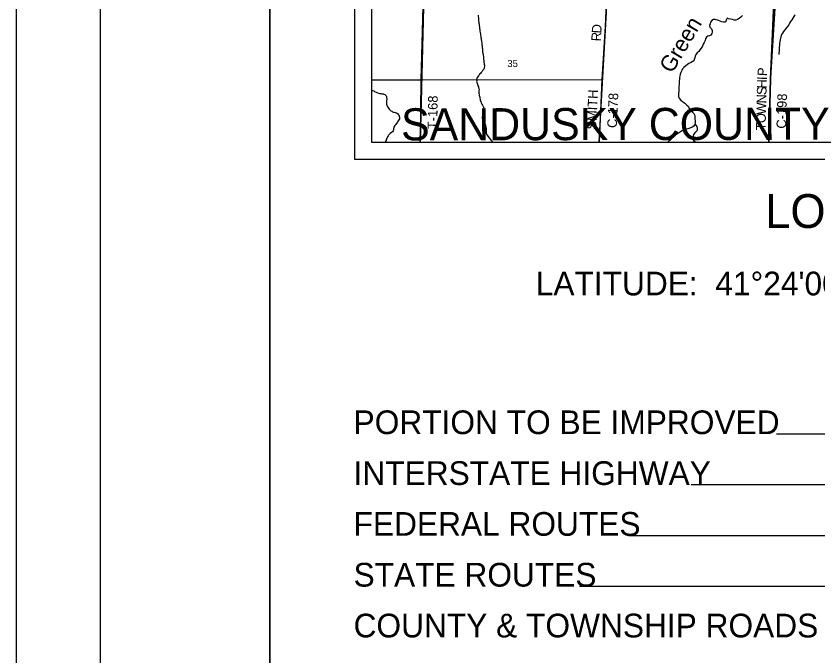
# Model space of a CAD drawing. Extents: x 36.7 to 70.7, y 0 to 22.
# Drawn here: x 36.693 to 41.432, y 11.064 to 14.842 of the extents above; entities that cross this region are included whole.
import ezdxf

# ---------------------------------------------------------------- set-up
doc = ezdxf.new("R2010")
doc.units = 0
for name, color, linetype in [('Default', 7, 'Continuous'), ('GM_X_County_Road', 7, 'Continuous'), ('GM_X_County_Road_Text', 7, 'Continuous'), ('GM_X_County_Text', 7, 'Continuous'), ('GM_X_Minor_River', 7, 'Continuous'), ('GM_X_Minor_River_Text', 7, 'Continuous'), ('GM_X_Section_Text', 7, 'Continuous'), ('GM_X_Township_Road', 7, 'Continuous'), ('GM_X_Township_Road_Text', 7, 'Continuous'), ('SH_Border', 7, 'Continuous'), ('SH_Cut_Line', 7, 'Continuous'), ('SH_Data', 7, 'Continuous'), ('SH_Text', 7, 'Continuous')]:
    doc.layers.add(name, color=color, linetype=linetype)

msp = doc.modelspace()

# ---------------------------------------------------------------- linework, layer by layer
at = {"layer": 'Default'}
for points in [[(38.7934, 14.9765), (38.7934, 14.0969), (39.082, 14.0969), (39.1038, 14.9743)], [(39.082, 14.0969), (40.1392, 14.0969), (40.1892, 14.9717), (39.1038, 14.9743)]]:
    msp.add_lwpolyline(points, close=True, dxfattribs=at)
at = {"layer": 'GM_X_County_Road'}
msp.add_line((41.1529, 14.4774), (41.1844, 14.9819), dxfattribs=at)
for points in [[(40.1402, 14.0969), (40.1568, 14.4677), (40.1766, 14.7804), (40.1853, 14.9672)], [(41.142, 14.0969), (41.1524, 14.4693), (41.1529, 14.4774)]]:
    msp.add_lwpolyline(points, dxfattribs=at)
at = {"layer": 'GM_X_Minor_River'}
for points in [[(39.4238, 14.8475), (39.4248, 14.8384), (39.4255, 14.8308), (39.4262, 14.8201), (39.4268, 14.8125), (39.4279, 14.8072), (39.4286, 14.8), (39.4293, 14.7931), (39.4307, 14.7848), (39.4314, 14.7802), (39.4325, 14.7741), (39.4328, 14.7684), (39.4335, 14.7616), (39.4334, 14.757), (39.4341, 14.7521), (39.4355, 14.7445), (39.4373, 14.7346), (39.4388, 14.7281), (39.4402, 14.7205), (39.4405, 14.716), (39.4416, 14.7084), (39.4426, 14.7023), (39.4433, 14.6973), (39.444, 14.6909), (39.4455, 14.6836), (39.4465, 14.6722), (39.4472, 14.6654), (39.4475, 14.6601), (39.4478, 14.6544), (39.4489, 14.6487), (39.4495, 14.6422), (39.4499, 14.6354), (39.4506, 14.6304), (39.4516, 14.6213), (39.4527, 14.6156), (39.4547, 14.5985), (39.4551, 14.5932), (39.4554, 14.5875), (39.4568, 14.5768), (39.4582, 14.5696), (39.46, 14.5628), (39.4603, 14.5574), (39.4607, 14.5525), (39.4614, 14.5468), (39.4605, 14.5381), (39.4589, 14.5328), (39.4566, 14.5283), (39.4524, 14.5226), (39.4477, 14.5154), (39.4427, 14.509), (39.4377, 14.503), (39.4324, 14.4978), (39.4293, 14.4932), (39.4254, 14.4887), (39.4185, 14.4786), (39.4158, 14.4733), (39.4149, 14.4664), (39.4153, 14.4611), (39.4152, 14.4558), (39.4163, 14.4505), (39.4173, 14.4448), (39.4192, 14.4398), (39.4229, 14.4307), (39.4254, 14.4234), (39.4269, 14.4181), (39.4295, 14.4101), (39.4275, 14.4018), (39.4281, 14.3942), (39.4284, 14.387), (39.4303, 14.3797)], [(40.9866, 14.8452), (40.9766, 14.8358), (40.9659, 14.8264), (40.9563, 14.8205), (40.9468, 14.8179), (40.9373, 14.8184), (40.9268, 14.8219), (40.9154, 14.8232), (40.9037, 14.8256), (40.895, 14.8287), (40.8903, 14.8166), (40.8849, 14.8064), (40.8742, 14.8062), (40.8648, 14.8074), (40.8534, 14.8121), (40.8447, 14.8148), (40.8243, 14.8211), (40.8137, 14.822), (40.8049, 14.8164), (40.7969, 14.8066), (40.7945, 14.7968), (40.7917, 14.7869), (40.7938, 14.7755), (40.8028, 14.7659), (40.8065, 14.7572), (40.8068, 14.7473), (40.804, 14.7386), (40.7998, 14.7299), (40.791, 14.7243), (40.7819, 14.724), (40.7727, 14.7177), (40.768, 14.7071), (40.7645, 14.6969), (40.7594, 14.6848), (40.754, 14.6757), (40.7493, 14.6636), (40.742, 14.6516), (40.7335, 14.6418), (40.7281, 14.632), (40.7189, 14.6249), (40.7112, 14.6151), (40.7069, 14.6045), (40.7038, 14.5954), (40.701, 14.5852), (40.6975, 14.5765), (40.6887, 14.5724), (40.678, 14.5653)], [(41.2961, 14.8498), (41.2896, 14.8396), (41.283, 14.8291), (41.2772, 14.82), (41.2699, 14.8099), (41.2641, 14.7989), (41.259, 14.7899), (41.2521, 14.7801), (41.2444, 14.771), (41.2275, 14.7504), (41.2221, 14.7413), (41.2174, 14.7322), (41.212, 14.7198), (41.2096, 14.7111), (41.208, 14.7008), (41.206, 14.691), (41.2047, 14.6819), (41.2039, 14.6728), (41.2036, 14.6534), (41.2028, 14.6432), (41.2019, 14.6345), (41.201, 14.6254), (41.1998, 14.6148)], [(40.678, 14.5653), (40.6693, 14.5624), (40.6605, 14.5564), (40.6505, 14.5482), (40.6394, 14.5388), (40.6317, 14.5298), (40.6278, 14.5207), (40.6216, 14.5094), (40.6181, 14.498), (40.6165, 14.487), (40.6145, 14.4783), (40.6132, 14.4685), (40.6112, 14.4578), (40.611, 14.4358), (40.6105, 14.4271), (40.6096, 14.4169), (40.6095, 14.4081), (40.609, 14.3964), (40.6085, 14.3865), (40.608, 14.3759), (40.6086, 14.3652), (40.6116, 14.3565), (40.619, 14.3473), (40.6337, 14.3361), (40.6458, 14.3284), (40.657, 14.3165), (40.666, 14.3069), (40.6712, 14.2951), (40.6805, 14.2851), (40.6895, 14.2759), (40.6985, 14.2656), (40.7045, 14.2538), (40.704, 14.2416), (40.7042, 14.2321), (40.706, 14.2234), (40.7071, 14.2139), (40.7039, 14.2014), (40.6985, 14.1919), (40.6882, 14.1867), (40.6756, 14.1797), (40.6634, 14.1768), (40.6516, 14.1735), (40.6394, 14.169), (40.6291, 14.1646), (40.6196, 14.1582), (40.6073, 14.1508), (40.5978, 14.1448), (40.589, 14.1369), (40.5786, 14.1268), (40.569, 14.1182), (40.5579, 14.1088), (40.5491, 14.1017), (40.5441, 14.0969)], [(38.7934, 14.4045), (38.799, 14.4032), (38.8073, 14.4), (38.8125, 14.3966), (38.8205, 14.3923), (38.8261, 14.3896), (38.8359, 14.3861), (38.842, 14.3845), (38.8488, 14.3837), (38.8549, 14.3828), (38.8621, 14.3824), (38.8666, 14.3808), (38.8719, 14.3785), (38.8764, 14.3754), (38.8809, 14.3712), (38.8816, 14.3662), (38.8831, 14.359), (38.8838, 14.3541), (38.8837, 14.348), (38.8829, 14.3427), (38.8828, 14.3381), (38.8828, 14.3324), (38.8827, 14.3271), (38.883, 14.321), (38.8848, 14.3153), (38.887, 14.31), (38.8904, 14.3035), (38.8949, 14.2985), (38.8982, 14.292), (38.9035, 14.2867), (38.9084, 14.2828), (38.9136, 14.2801)], [(39.4303, 14.3797), (39.4306, 14.3737), (39.432, 14.3679), (39.4331, 14.3626), (39.4349, 14.3561), (39.436, 14.3485), (39.4367, 14.3428), (39.4393, 14.3367), (39.4415, 14.3295), (39.4463, 14.3226), (39.45, 14.3157), (39.4537, 14.3085), (39.4563, 14.3035), (39.4578, 14.2982), (39.4592, 14.2917), (39.4595, 14.2857), (39.4595, 14.2796), (39.4583, 14.2739), (39.4555, 14.2663), (39.452, 14.2592), (39.4497, 14.2501), (39.4484, 14.244), (39.448, 14.2372), (39.449, 14.23), (39.4513, 14.2239), (39.4561, 14.22), (39.4591, 14.2154), (39.461, 14.2105), (39.4654, 14.204), (39.4673, 14.1971), (39.4698, 14.1868), (39.4712, 14.177), (39.4715, 14.1724), (39.4711, 14.1675), (39.4714, 14.158), (39.472, 14.1511), (39.4731, 14.1458), (39.475, 14.1397), (39.4824, 14.1309), (39.4869, 14.1252), (39.4914, 14.1206), (39.4948, 14.1156), (39.4993, 14.1095), (39.5022, 14.1049), (39.506, 14.0995), (39.5077, 14.0969)], [(38.9136, 14.2801), (38.9185, 14.277), (38.9238, 14.275), (38.9287, 14.2735), (38.9333, 14.2723), (38.9378, 14.2711), (38.9424, 14.2695), (38.948, 14.2668), (38.954, 14.2592), (38.9574, 14.2546), (38.9581, 14.2496), (38.9587, 14.242), (38.9583, 14.2348), (38.9548, 14.2288), (38.9509, 14.2224), (38.9474, 14.2171), (38.9447, 14.2126), (38.9409, 14.2073), (38.9367, 14.2024), (38.9309, 14.1953), (38.9266, 14.1862), (38.9238, 14.1756), (38.9234, 14.1695), (38.921, 14.1635), (38.9176, 14.1582), (38.9122, 14.1548), (38.9046, 14.1492), (38.8996, 14.1451), (38.8946, 14.1387), (38.8915, 14.1342), (38.8892, 14.1293), (38.8872, 14.1247), (38.8853, 14.1198), (38.8814, 14.1126), (38.8802, 14.107), (38.8748, 14.0987), (38.8739, 14.0969)], [(40.7051, 14.2063), (40.7095, 14.1983), (40.7163, 14.1891), (40.7188, 14.1792), (40.7179, 14.1686), (40.7136, 14.1595), (40.7048, 14.1532), (40.6968, 14.1434), (40.6944, 14.1331), (40.6931, 14.1244), (40.6927, 14.1149), (40.6982, 14.1046), (40.7084, 14.1), (40.711, 14.0969)]]:
    msp.add_lwpolyline(points, dxfattribs=at)
at = {"layer": 'GM_X_Township_Road'}
for points in [[(38.7934, 19.8608), (38.7934, 14.0969), (41.1418, 14.0969), (41.1522, 14.4699), (41.174, 14.9671)], [(41.174, 14.9671), (41.1522, 14.4699), (41.1418, 14.0969), (45.5934, 14.0969), (45.5934, 19.8832)], [(39.083, 14.0969), (39.0873, 14.4651), (39.1004, 14.9709)], [(38.7934, 14.4658), (39.0873, 14.4651), (40.1568, 14.4677)]]:
    msp.add_lwpolyline(points, dxfattribs=at)
at = {"layer": 'SH_Border'}
for points in [[(37.1934, 21.4969), (38.1934, 21.4969), (38.1934, 0.4969), (37.1934, 0.4969)], [(38.1934, 21.4969), (70.1934, 21.4969), (70.1934, 0.4969), (38.1934, 0.4969)]]:
    msp.add_lwpolyline(points, close=True, dxfattribs=at)
at = {"layer": 'SH_Cut_Line'}
msp.add_lwpolyline([(36.6934, -0.0031), (70.6934, -0.0031), (70.6934, 21.9969), (36.6934, 21.9969)], close=True, dxfattribs=at)
at = {"layer": 'SH_Data'}
for p, q in [((38.6934, 20.9969), (38.6934, 13.9969)), ((38.7934, 20.8969), (38.7934, 14.0969)), ((38.7934, 14.0969), (45.5934, 14.0969)), ((38.7934, 14.0969), (38.7934, 14.0969)), ((38.6934, 13.9969), (45.6934, 13.9969)), ((44.3934, 12.3736), (41.1871, 12.3736)), ((44.3934, 12.0736), (40.6829, 12.0736)), ((44.3934, 11.7736), (40.3126, 11.7736)), ((44.3934, 11.4736), (40.0222, 11.4736))]:
    msp.add_line(p, q, dxfattribs=at)

# ---------------------------------------------------------------- texts
at = {"layer": 'GM_X_County_Road_Text'}
for s, height, rotation, p in [('D', 0.0568, 86.4825, (40.1516, 14.7379)), ('R', 0.0568, 86.8175, (40.149, 14.6914)), ('P', 0.0568, 86.7578, (41.1309, 14.486)), ('H', 0.0568, 88.2803, (41.1284, 14.4131)), ('I', 0.0568, 87.5716, (41.1299, 14.4629)), ('S', 0.0568, 88.5833, (41.1274, 14.3748)), ('SMITH', 0.05682, 87.347, (40.1215, 14.1704)), ('C-178', 0.05682, 87.5227, (40.2433, 14.1801)), ('N', 0.0568, 88.5828, (41.1262, 14.3249)), ('C-198', 0.05682, 88.3475, (41.2433, 14.1765)), ('W', 0.0568, 88.5833, (41.1246, 14.259)), ('O', 0.0568, 88.5828, (41.1233, 14.2091)), ('T', 0.0568, 88.5856, (41.1223, 14.1666))]:
    msp.add_text(s, height=height, rotation=rotation, dxfattribs=at).set_placement(p)
at = {"layer": 'GM_X_County_Text'}
msp.add_text('SANDUSKY COUNTY', height=0.189394, rotation=0.0833, dxfattribs=at).set_placement((38.9687, 14.1078))
at = {"layer": 'GM_X_Minor_River_Text'}
msp.add_text('Green', height=0.09475, rotation=59.3515, dxfattribs=at).set_placement((40.5704, 14.4984))
at = {"layer": 'GM_X_Section_Text'}
msp.add_text('35', height=0.04186, rotation=0, dxfattribs=at).set_placement((39.5963, 14.5407))
at = {"layer": 'GM_X_Township_Road_Text'}
msp.add_text('T-168', height=0.05682, rotation=89.1579, dxfattribs=at).set_placement((39.1824, 14.1737))
at = {"layer": 'SH_Text'}
for s, height, p in [('LOCATION MAP', 0.2, (41.1203, 13.5907)), ('LATITUDE:  41°24\'00"     LONGITUDE:  83°06\'00"', 0.14, (39.7644, 13.1928)), ('PORTION TO BE IMPROVED', 0.14, (38.6878, 12.3736)), ('INTERSTATE HIGHWAY', 0.14, (38.6878, 12.0736)), ('FEDERAL ROUTES', 0.14, (38.6878, 11.7736)), ('STATE ROUTES', 0.14, (38.6878, 11.4736)), ('COUNTY & TOWNSHIP ROADS', 0.14, (38.6878, 11.1736))]:
    msp.add_text(s, height=height, dxfattribs=at).set_placement(p)

doc.saveas('drawing.dxf')
